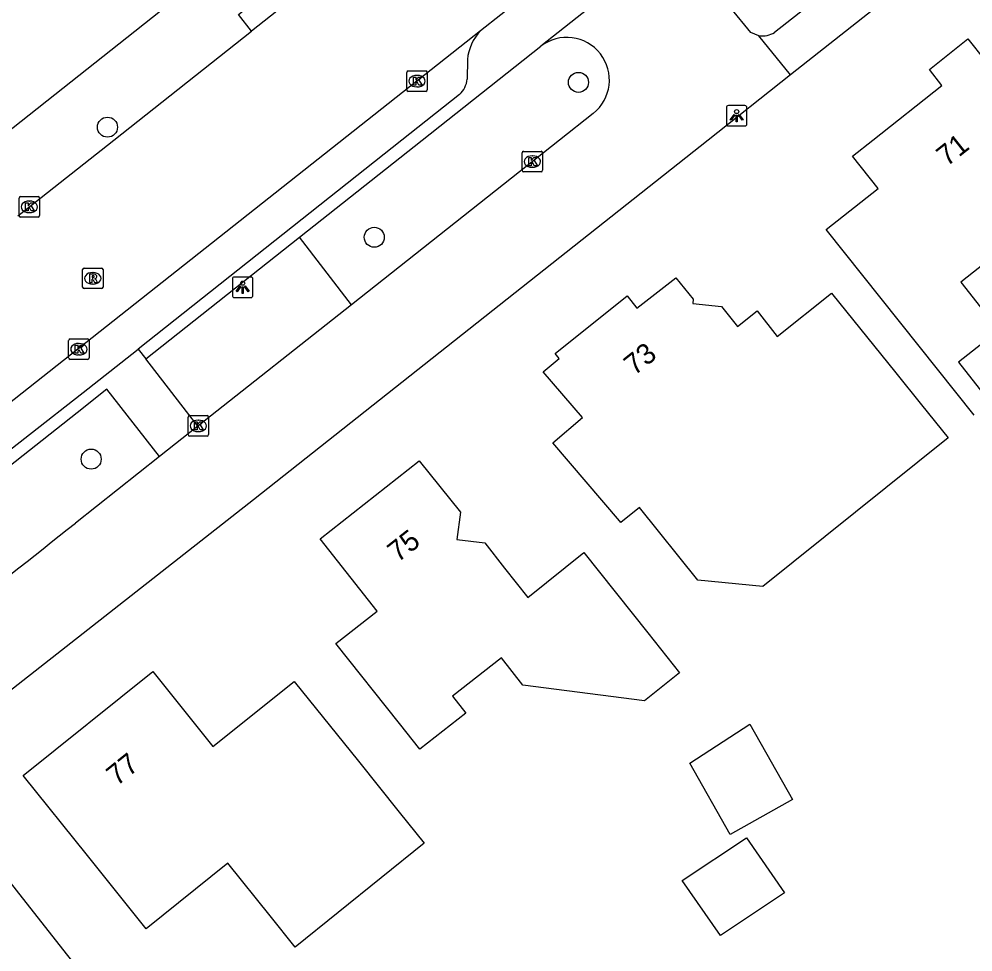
# Model space of a CAD drawing. Extents: x 159503 to 160347, y 382525 to 383272.
# Drawn here: x 159794.13 to 159840.68, y 382960.37 to 383005.91 of the extents above; entities that cross this region are included whole.
import ezdxf

# ---------------------------------------------------------------- set-up
doc = ezdxf.new("R2010")
doc.units = 0
for name, color, linetype in [('IMGEO_Boom', 7, 'Continuous'), ('IMGEO_Groenvoorziening', 7, 'Continuous'), ('IMGEO_Kolk', 7, 'Continuous'), ('IMGEO_Lichtpunt', 7, 'Continuous'), ('IMGEO_Pand', 7, 'Continuous'), ('IMGEO_Pand_nummerreeks', 7, 'Continuous'), ('IMGEO_Rijbaan_lokaal_open', 7, 'Continuous'), ('IMGEO_Rioolput', 7, 'Continuous'), ('IMGEO_Voetpad_open', 7, 'Continuous')]:
    doc.layers.add(name, color=color, linetype=linetype)

msp = doc.modelspace()

# ---------------------------------------------------------------- linework, layer by layer
at = {"layer": 'IMGEO_Boom'}
for centre in [(159821.429, 383002.82), (159798.444, 383000.632), (159811.466, 382995.255), (159797.649, 382984.426)]:
    msp.add_circle(centre, 0.489, dxfattribs=at)
at = {"layer": 'IMGEO_Groenvoorziening'}
msp.add_lwpolyline([(159810.35, 382991.964), (159807.81, 382995.257)], dxfattribs=at)
at = {"layer": 'IMGEO_Kolk'}
for p, q in [((159813.05, 383002.453), (159813.05, 383003.305)), ((159813.125, 383003.379), (159813.977, 383003.379)), ((159813.538, 383003.159), (159813.563, 383003.159)), ((159814.051, 383003.305), (159814.051, 383002.453)), ((159813.561, 383002.599), (159813.536, 383002.599)), ((159813.977, 383002.379), (159813.125, 383002.379)), ((159818.679, 382998.526), (159818.679, 382999.378)), ((159818.754, 382999.452), (159819.606, 382999.452)), ((159819.68, 382999.378), (159819.68, 382998.526)), ((159819.167, 382999.232), (159819.192, 382999.232)), ((159819.606, 382998.452), (159818.754, 382998.452)), ((159819.19, 382998.672), (159819.165, 382998.672)), ((159794.13, 382996.316), (159794.13, 382997.168)), ((159794.205, 382997.242), (159795.057, 382997.242)), ((159794.618, 382997.022), (159794.643, 382997.022)), ((159795.131, 382997.168), (159795.131, 382996.316)), ((159795.057, 382996.242), (159794.205, 382996.242)), ((159794.641, 382996.462), (159794.616, 382996.462)), ((159796.55, 382989.366), (159796.55, 382990.218)), ((159796.625, 382990.292), (159797.477, 382990.292)), ((159797.038, 382990.072), (159797.063, 382990.072)), ((159797.551, 382990.218), (159797.551, 382989.366)), ((159797.061, 382989.512), (159797.036, 382989.512)), ((159797.477, 382989.292), (159796.625, 382989.292)), ((159802.377, 382985.622), (159802.377, 382986.474)), ((159802.452, 382986.548), (159803.304, 382986.548)), ((159802.865, 382986.328), (159802.89, 382986.328)), ((159803.378, 382986.474), (159803.378, 382985.622)), ((159803.304, 382985.548), (159802.452, 382985.548)), ((159802.888, 382985.768), (159802.863, 382985.768))]:
    msp.add_line(p, q, dxfattribs=at)
for points in [[(159813.05, 383002.453), (159813.05, 383003.305)], [(159813.125, 383003.379), (159813.977, 383003.379)], [(159813.371, 383003.079), (159813.494, 383003.079), (159813.494, 383002.928), (159813.624, 383003.079), (159813.788, 383003.079), (159813.642, 383002.928), (159813.795, 383002.679), (159813.643, 383002.679), (159813.558, 383002.843), (159813.494, 383002.776), (159813.494, 383002.679), (159813.371, 383002.679), (159813.371, 383003.079)], [(159814.051, 383003.305), (159814.051, 383002.453)], [(159813.977, 383002.379), (159813.125, 383002.379)], [(159818.679, 382998.526), (159818.679, 382999.378)], [(159818.754, 382999.452), (159819.606, 382999.452)], [(159819.68, 382999.378), (159819.68, 382998.526)], [(159819, 382999.152), (159819.123, 382999.152), (159819.123, 382999.001), (159819.253, 382999.152), (159819.417, 382999.152), (159819.271, 382999.001), (159819.424, 382998.752), (159819.272, 382998.752), (159819.187, 382998.916), (159819.123, 382998.849), (159819.123, 382998.752), (159819, 382998.752), (159819, 382999.152)], [(159819.606, 382998.452), (159818.754, 382998.452)], [(159794.13, 382996.316), (159794.13, 382997.168)], [(159794.205, 382997.242), (159795.057, 382997.242)], [(159795.131, 382997.168), (159795.131, 382996.316)], [(159794.451, 382996.942), (159794.574, 382996.942), (159794.574, 382996.791), (159794.704, 382996.942), (159794.868, 382996.942), (159794.722, 382996.791), (159794.875, 382996.542), (159794.723, 382996.542), (159794.638, 382996.706), (159794.574, 382996.639), (159794.574, 382996.542), (159794.451, 382996.542), (159794.451, 382996.942)], [(159795.057, 382996.242), (159794.205, 382996.242)], [(159796.55, 382989.366), (159796.55, 382990.218)], [(159796.625, 382990.292), (159797.477, 382990.292)], [(159796.871, 382989.992), (159796.994, 382989.992), (159796.994, 382989.841), (159797.124, 382989.992), (159797.288, 382989.992), (159797.142, 382989.841), (159797.295, 382989.592), (159797.143, 382989.592), (159797.058, 382989.756), (159796.994, 382989.689), (159796.994, 382989.592), (159796.871, 382989.592), (159796.871, 382989.992)], [(159797.551, 382990.218), (159797.551, 382989.366)], [(159797.477, 382989.292), (159796.625, 382989.292)], [(159802.377, 382985.622), (159802.377, 382986.474)], [(159802.452, 382986.548), (159803.304, 382986.548)], [(159803.378, 382986.474), (159803.378, 382985.622)], [(159802.698, 382986.248), (159802.821, 382986.248), (159802.821, 382986.097), (159802.951, 382986.248), (159803.115, 382986.248), (159802.969, 382986.097), (159803.122, 382985.848), (159802.97, 382985.848), (159802.885, 382986.012), (159802.821, 382985.945), (159802.821, 382985.848), (159802.698, 382985.848), (159802.698, 382986.248)], [(159803.304, 382985.548), (159802.452, 382985.548)]]:
    msp.add_lwpolyline(points, dxfattribs=at)
for centre, start, end in [((159813.127, 383003.303), 91.552, 178.448), ((159813.127, 383003.303), 91.552, 178.448), ((159813.975, 383003.303), 1.552, 88.448), ((159813.975, 383003.303), 1.552, 88.448), ((159813.127, 383002.455), 181.552, 268.448), ((159813.127, 383002.455), 181.552, 268.448), ((159813.975, 383002.455), 271.552, 358.448), ((159813.975, 383002.455), 271.552, 358.448), ((159818.756, 382999.376), 91.552, 178.448), ((159818.756, 382999.376), 91.552, 178.448), ((159819.604, 382999.376), 1.552, 88.448), ((159819.604, 382999.376), 1.552, 88.448), ((159818.756, 382998.528), 181.552, 268.448), ((159818.756, 382998.528), 181.552, 268.448), ((159819.604, 382998.528), 271.552, 358.448), ((159819.604, 382998.528), 271.552, 358.448), ((159794.207, 382997.166), 91.552, 178.448), ((159794.207, 382997.166), 91.552, 178.448), ((159795.055, 382997.166), 1.552, 88.448), ((159795.055, 382997.166), 1.552, 88.448), ((159794.207, 382996.318), 181.552, 268.448), ((159794.207, 382996.318), 181.552, 268.448), ((159795.055, 382996.318), 271.552, 358.448), ((159795.055, 382996.318), 271.552, 358.448), ((159796.627, 382990.216), 91.552, 178.448), ((159796.627, 382990.216), 91.552, 178.448), ((159797.475, 382990.216), 1.552, 88.448), ((159797.475, 382990.216), 1.552, 88.448), ((159796.627, 382989.368), 181.552, 268.448), ((159796.627, 382989.368), 181.552, 268.448), ((159797.475, 382989.368), 271.552, 358.448), ((159797.475, 382989.368), 271.552, 358.448), ((159802.454, 382986.472), 91.552, 178.448), ((159802.454, 382986.472), 91.552, 178.448), ((159803.302, 382986.472), 1.552, 88.448), ((159803.302, 382986.472), 1.552, 88.448), ((159802.454, 382985.624), 181.552, 268.448), ((159802.454, 382985.624), 181.552, 268.448), ((159803.302, 382985.624), 271.552, 358.448), ((159803.302, 382985.624), 271.552, 358.448)]:
    msp.add_arc(centre, 0.0765, start, end, dxfattribs=at)
for centre, major_axis, ratio, start_param, end_param in [((159813.537, 383002.879), (-0.387, 0.002), 0.722429, 4.712389, 7.853982), ((159813.562, 383002.879), (-0.39, 0.002), 0.717154, 1.570796, 4.712389), ((159819.166, 382998.952), (-0.387, 0.002), 0.722429, 4.712389, 7.853982), ((159819.191, 382998.952), (-0.39, 0.002), 0.717154, 1.570796, 4.712389), ((159794.617, 382996.742), (-0.387, 0.002), 0.722429, 4.712389, 7.853982), ((159794.642, 382996.742), (-0.39, 0.002), 0.717154, 1.570796, 4.712389), ((159797.037, 382989.792), (-0.387, 0.002), 0.722429, 4.712389, 7.853982), ((159797.062, 382989.792), (-0.39, 0.002), 0.717154, 1.570796, 4.712389), ((159802.864, 382986.048), (-0.387, 0.002), 0.722429, 4.712389, 7.853982), ((159802.889, 382986.048), (-0.39, 0.002), 0.717154, 1.570796, 4.712389)]:
    msp.add_ellipse(centre, major_axis=major_axis, ratio=ratio, start_param=start_param, end_param=end_param, dxfattribs=at)
at = {"layer": 'IMGEO_Lichtpunt'}
for p, q in [((159829.552, 383001.689), (159828.744, 383001.689)), ((159829.552, 383001.689), (159828.744, 383001.689)), ((159828.65, 383001.594), (159828.65, 383000.787)), ((159828.65, 383001.594), (159828.65, 383000.787)), ((159829.646, 383000.787), (159829.646, 383001.594)), ((159829.646, 383000.787), (159829.646, 383001.594)), ((159828.744, 383000.693), (159829.552, 383000.693)), ((159828.744, 383000.693), (159829.552, 383000.693)), ((159805.445, 382993.313), (159804.637, 382993.313)), ((159805.445, 382993.313), (159804.637, 382993.313)), ((159804.543, 382993.218), (159804.543, 382992.411)), ((159804.543, 382993.218), (159804.543, 382992.411)), ((159805.539, 382992.411), (159805.539, 382993.218)), ((159805.539, 382992.411), (159805.539, 382993.218)), ((159804.637, 382992.317), (159805.445, 382992.317)), ((159804.637, 382992.317), (159805.445, 382992.317))]:
    msp.add_line(p, q, dxfattribs=at)
for points in [[(159829.024, 383001.258), (159829.063, 383001.23), (159828.875, 383000.968), (159828.837, 383000.995), (159829.024, 383001.258)], [(159829.126, 383001.21), (159829.173, 383001.21), (159829.173, 383000.888), (159829.126, 383000.888), (159829.126, 383001.21)], [(159829.236, 383001.23), (159829.274, 383001.257), (159829.461, 383000.995), (159829.422, 383000.967), (159829.236, 383001.23)], [(159804.917, 382992.882), (159804.956, 382992.854), (159804.768, 382992.592), (159804.73, 382992.619), (159804.917, 382992.882)], [(159805.019, 382992.834), (159805.066, 382992.834), (159805.066, 382992.512), (159805.019, 382992.512), (159805.019, 382992.834)], [(159805.129, 382992.854), (159805.167, 382992.881), (159805.354, 382992.619), (159805.315, 382992.591), (159805.129, 382992.854)]]:
    msp.add_lwpolyline(points, dxfattribs=at)
for centre in [(159829.149, 383001.392), (159805.042, 382993.016)]:
    msp.add_circle(centre, 0.0994, dxfattribs=at)
for centre, start, end in [((159828.744, 383001.594), 90, 180), ((159828.744, 383001.594), 90, 180), ((159829.552, 383001.594), 0, 90), ((159829.552, 383001.594), 0, 90), ((159828.744, 383000.787), 180, 270), ((159828.744, 383000.787), 180, 270), ((159829.552, 383000.787), 270, 0), ((159829.552, 383000.787), 270, 360), ((159804.637, 382993.218), 90, 180), ((159804.637, 382993.218), 90, 180), ((159805.445, 382993.218), 0, 90), ((159805.445, 382993.218), 0, 90), ((159804.637, 382992.411), 180, 270), ((159804.637, 382992.411), 180, 270), ((159805.445, 382992.411), 270, 0), ((159805.445, 382992.411), 270, 360)]:
    msp.add_arc(centre, 0.0946, start, end, dxfattribs=at)
at = {"layer": 'IMGEO_Pand'}
for points in [[(159840.736, 382986.578), (159833.521, 382995.63), (159836.052, 382997.636), (159834.804, 382999.211), (159835.798, 383000), (159839.163, 383002.672), (159838.564, 383003.45), (159840.434, 383004.946), (159842.092, 383002.863)], [(159843.024, 382995.378), (159840.085, 382993.065), (159841.94, 382990.707), (159839.976, 382989.161), (159841.522, 382987.196)], [(159824.406, 382982.059), (159823.502, 382981.332), (159823.427, 382981.419), (159820.175, 382985.217), (159821.618, 382986.452), (159819.703, 382988.687), (159820.493, 382989.344), (159820.289, 382989.59), (159823.801, 382992.391), (159824.277, 382991.794), (159826.173, 382993.273), (159827.021, 382992.227), (159827.014, 382992.027), (159828.409, 382991.88), (159829.197, 382990.903), (159830.144, 382991.663), (159831.132, 382990.407), (159833.784, 382992.535), (159836.915, 382988.637), (159838.167, 382987.077), (159839.463, 382985.463), (159830.422, 382978.207), (159827.259, 382978.512), (159824.406, 382982.059)], [(159813.692, 382970.267), (159812.703, 382971.512), (159809.594, 382975.428), (159811.598, 382977.004), (159808.816, 382980.541), (159813.658, 382984.348), (159815.67, 382981.832), (159815.493, 382980.497), (159816.854, 382980.335), (159817.825, 382979.104), (159818.952, 382977.675), (159821.692, 382979.859), (159824.809, 382975.95), (159826.367, 382973.995), (159824.647, 382972.624), (159818.721, 382973.382), (159817.67, 382974.718), (159815.288, 382972.846), (159815.931, 382972.029), (159813.692, 382970.267)], [(159810.687, 382969.677), (159812.684, 382967.19), (159813.906, 382965.668), (159807.597, 382960.604), (159806.377, 382962.124), (159804.314, 382964.694), (159800.336, 382961.498), (159797.462, 382965.076), (159794.331, 382968.974), (159800.665, 382974.051), (159803.594, 382970.401), (159807.555, 382973.575), (159810.687, 382969.677)], [(159826.864, 382969.575), (159829.8, 382971.482), (159831.873, 382967.814), (159828.832, 382966.095), (159826.864, 382969.575)], [(159829.625, 382965.936), (159831.488, 382963.248), (159828.357, 382961.164), (159826.494, 382963.852), (159829.625, 382965.936)], [(159794.624, 382952.871), (159792.6, 382955.435), (159790.441, 382953.791), (159786.863, 382950.869), (159785.932, 382952.032), (159783.247, 382955.407), (159784.694, 382956.548), (159782.157, 382959.73), (159788.342, 382964.777), (159789.658, 382963.096), (159790.599, 382961.893), (159792.824, 382963.647), (159791.811, 382964.834), (159792.433, 382965.349), (159795.526, 382961.42), (159799.369, 382956.536), (159798.582, 382955.928), (159794.624, 382952.871)]]:
    msp.add_lwpolyline(points, dxfattribs=at)
at = {"layer": 'IMGEO_Rijbaan_lokaal_open'}
for points in [[(159828.299, 383011.476), (159819.587, 383004.581)], [(159830.239, 383005.093), (159829.835, 383005.251), (159827.929, 383007.611), (159827.778, 383008.07), (159827.59, 383009.566)], [(159810.572, 383009.347), (159805.481, 383005.321)], [(159818.638, 383006.917), (159816.646, 383005.334)], [(159816.646, 383005.334), (159784.946, 382980.27), (159777.634, 382974.895)], [(159794.077, 382996.304), (159794.355, 382996.523), (159798.752, 383000), (159805.481, 383005.321)], [(159831.784, 383003.185), (159830.239, 383005.093)], [(159831.784, 383003.185), (159827.76, 383000), (159805.571, 382982.438), (159791.729, 382971.586)], [(159822.147, 383001.302), (159820.502, 383000), (159810.35, 382991.964)], [(159810.35, 382991.964), (159802.862, 382986.037)], [(159802.862, 382986.037), (159800.978, 382984.561)], [(159800.978, 382984.561), (159796.876, 382981.305)]]:
    msp.add_lwpolyline(points, dxfattribs=at)
for centre, radius, start, end in [((159820.857, 383002.934), 2.08, 308.3363, 127.6239), ((159553.608, 383284.554), 388.767, 306.36737, 308.73678)]:
    msp.add_arc(centre, radius, start, end, dxfattribs=at)
at = {"layer": 'IMGEO_Rioolput'}
for p, q in [((159797.304, 382993.753), (159798.156, 382993.753)), ((159797.229, 382992.827), (159797.229, 382993.679)), ((159797.717, 382993.533), (159797.742, 382993.533)), ((159798.23, 382993.679), (159798.23, 382992.827)), ((159797.74, 382992.973), (159797.715, 382992.973)), ((159798.156, 382992.753), (159797.304, 382992.753))]:
    msp.add_line(p, q, dxfattribs=at)
for points in [[(159797.304, 382993.753), (159798.156, 382993.753)], [(159797.229, 382992.827), (159797.229, 382993.679)], [(159797.818, 382993.451), (159797.566, 382993.453), (159797.566, 382993.053)], [(159797.744, 382993.372), (159797.69, 382993.372), (159797.69, 382993.291)], [(159797.69, 382993.291), (159797.742, 382993.291)], [(159798.23, 382993.679), (159798.23, 382992.827)], [(159797.566, 382993.053), (159797.69, 382993.053), (159797.69, 382993.215), (159797.701, 382993.215)], [(159797.748, 382993.186), (159797.819, 382993.053), (159797.959, 382993.053), (159797.894, 382993.179)], [(159798.156, 382992.753), (159797.304, 382992.753)]]:
    msp.add_lwpolyline(points, dxfattribs=at)
for centre, radius, start, end in [((159797.306, 382993.677), 0.0765, 91.552, 178.448), ((159797.306, 382993.677), 0.0765, 91.552, 178.448), ((159798.154, 382993.677), 0.0765, 1.552, 88.448), ((159798.154, 382993.677), 0.0765, 1.552, 88.448), ((159797.726, 382993.48), 0.19, 274.7715, 282.9687), ((159797.75, 382993.276), 0.0964, 77.0061, 93.1865), ((159797.764, 382993.333), 0.0378, 276.6634, 79.6772), ((159797.817, 382993.341), 0.109, 350.3612, 89.416), ((159797.815, 382993.341), 0.112, 277.5842, 350.9817), ((159797.306, 382992.829), 0.0765, 181.552, 268.448), ((159797.306, 382992.829), 0.0765, 181.552, 268.448), ((159797.7, 382993.162), 0.0533, 26.0293, 88.6989), ((159797.799, 382993.126), 0.108, 29.5134, 73.7905), ((159798.154, 382992.829), 0.0765, 271.552, 358.448), ((159798.154, 382992.829), 0.0765, 271.552, 358.448)]:
    msp.add_arc(centre, radius, start, end, dxfattribs=at)
for centre, major_axis, ratio, start_param, end_param in [((159797.716, 382993.253), (-0.387, 0.002), 0.722429, 4.712389, 7.853982), ((159797.741, 382993.253), (-0.39, 0.002), 0.717154, 1.570796, 4.712389)]:
    msp.add_ellipse(centre, major_axis=major_axis, ratio=ratio, start_param=start_param, end_param=end_param, dxfattribs=at)
at = {"layer": 'IMGEO_Voetpad_open'}
for points in [[(159774.942, 382985.649), (159793.053, 383000), (159824.858, 383025.202)], [(159848.163, 383005.646), (159842.05, 383011.31), (159831.784, 383003.185)], [(159837.988, 383010.753), (159831.002, 383005.256)], [(159805.481, 383005.321), (159804.836, 383006.137), (159809.927, 383010.163), (159810.572, 383009.347)], [(159807.81, 382995.257), (159813.801, 383000), (159819.587, 383004.581)], [(159816.008, 383003.929), (159816, 383002.98)], [(159815.625, 383002.231), (159812.811, 383000), (159799.938, 382989.792)], [(159800.322, 382989.329), (159807.81, 382995.257)], [(159780.772, 382974.903), (159785.179, 382978.223), (159797.492, 382987.853), (159799.938, 382989.792)], [(159799.938, 382989.792), (159800.322, 382989.329)], [(159802.862, 382986.037), (159800.322, 382989.329)], [(159800.978, 382984.561), (159798.414, 382987.84), (159796.969, 382986.685), (159787.262, 382979.025)]]:
    msp.add_lwpolyline(points, dxfattribs=at)
for centre, radius, start, end in [((159818.376, 383003.701), 2.379, 136.6502, 174.5049), ((159830.394, 383006.235), 1.152, 262.2654, 301.8523), ((159814.824, 383003.1), 1.182, 312.6493, 354.1594)]:
    msp.add_arc(centre, radius, start, end, dxfattribs=at)

# ---------------------------------------------------------------- texts
at = {"layer": 'IMGEO_Pand_nummerreeks'}
for s, rotation, p in [('71', 38.4702, (159839.409, 382998.681)), ('73', 38.5742, (159824.157, 382988.478)), ('75', 38.176, (159812.614, 382979.355)), ('77', 38.7138, (159798.905, 382968.437))]:
    msp.add_text(s, height=1, rotation=rotation, dxfattribs=at).set_placement(p)

doc.saveas('drawing.dxf')
